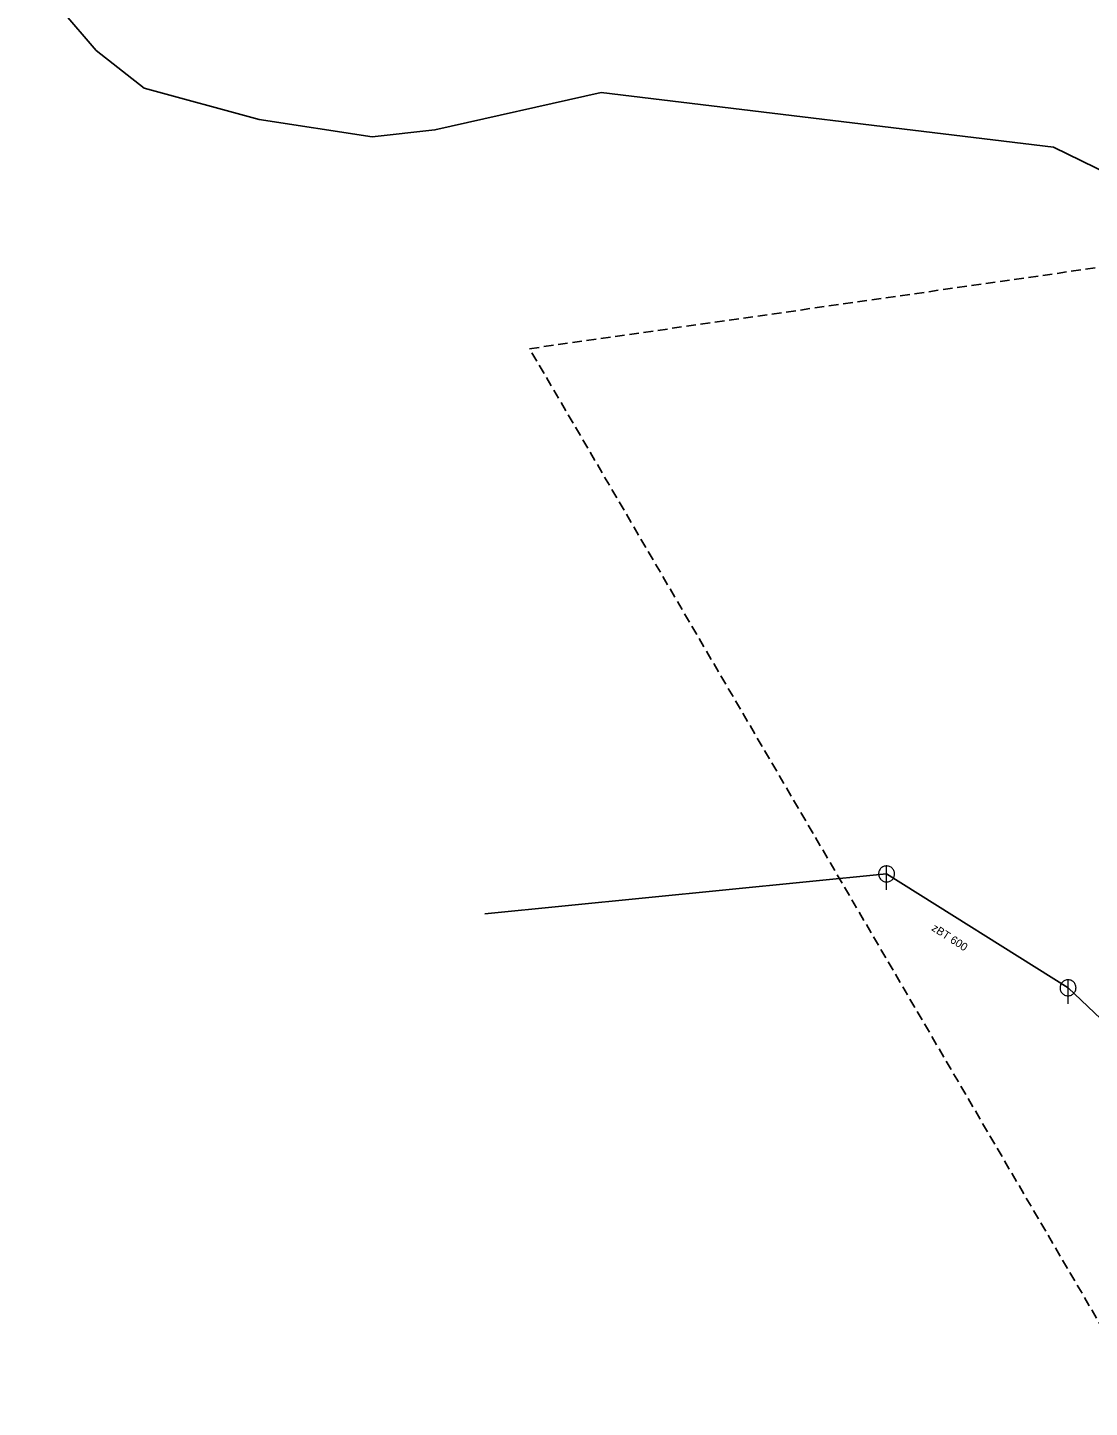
# Model space of a CAD drawing. Extents: x -687016 to -686065, y -974192 to -973552.
# Drawn here: x -686381.1 to -686248.4, y -973940.5 to -973768.1 of the extents above; entities that cross this region are included whole.
import ezdxf

# ---------------------------------------------------------------- set-up
doc = ezdxf.new("R2010")
doc.units = 0
doc.header["$LTSCALE"] = 0.4
doc.linetypes.add('MEDIUM_DASHED', pattern=[4.5, 3, -1.5])
doc.layers.add('1', color=7, linetype='Continuous')
for name, color, linetype, lineweight in [('14', 7, 'Continuous', 25), ('17', 7, 'Continuous', 25), ('22', 7, 'Continuous', 13), ('63', 7, 'MEDIUM_DASHED', 25)]:
    doc.layers.add(name, color=color, linetype=linetype, lineweight=lineweight)

msp = doc.modelspace()

# ---------------------------------------------------------------- linework, layer by layer
at = {"layer": '14'}
for p, q in [((-686273.734, -973873.852), (-686323.946, -973878.859)), ((-686251.059, -973888.086), (-686273.734, -973873.852)), ((-686232.891, -973905.396), (-686251.059, -973888.086))]:
    msp.add_line(p, q, dxfattribs=at)
at = {"layer": '17'}
msp.add_lwpolyline([(-686191.62, -973832.066), (-686200.045, -973808.813), (-686252.856, -973783.01), (-686309.416, -973776.191), (-686330.193, -973780.853), (-686338.011, -973781.713), (-686352.154, -973779.531), (-686366.52, -973775.649), (-686372.52, -973770.94), (-686381.099, -973760.889)], dxfattribs=at)
at = {"layer": '22'}
for p, q in [((-686273.734, -973875.852), (-686273.733, -973872.852)), ((-686251.059, -973890.086), (-686251.058, -973887.086))]:
    msp.add_line(p, q, dxfattribs=at)
for points in [[(-686272.734, -973873.852), (-686272.739, -973873.743), (-686272.757, -973873.635), (-686272.787, -973873.529), (-686272.827, -973873.428), (-686272.879, -973873.331), (-686272.941, -973873.241), (-686273.013, -973873.158), (-686273.093, -973873.084), (-686273.181, -973873.018), (-686273.275, -973872.963), (-686273.375, -973872.918), (-686273.48, -973872.885), (-686273.587, -973872.863), (-686273.696, -973872.853), (-686273.806, -973872.855), (-686273.914, -973872.869), (-686274.021, -973872.894), (-686274.124, -973872.931), (-686274.222, -973872.98), (-686274.314, -973873.038), (-686274.4, -973873.107), (-686274.477, -973873.184), (-686274.546, -973873.27), (-686274.605, -973873.362), (-686274.653, -973873.46), (-686274.69, -973873.563), (-686274.716, -973873.67), (-686274.73, -973873.778), (-686274.733, -973873.888), (-686274.723, -973873.997), (-686274.702, -973874.104), (-686274.668, -973874.208), (-686274.624, -973874.308), (-686274.569, -973874.403), (-686274.503, -973874.491), (-686274.429, -973874.571), (-686274.346, -973874.643), (-686274.256, -973874.705), (-686274.16, -973874.757), (-686274.058, -973874.798), (-686273.953, -973874.828), (-686273.845, -973874.846), (-686273.735, -973874.852), (-686273.626, -973874.846), (-686273.518, -973874.828), (-686273.413, -973874.799), (-686273.311, -973874.758), (-686273.214, -973874.706), (-686273.124, -973874.644), (-686273.041, -973874.573), (-686272.966, -973874.493), (-686272.901, -973874.405), (-686272.845, -973874.311), (-686272.801, -973874.211), (-686272.767, -973874.107), (-686272.745, -973873.999), (-686272.735, -973873.89)], [(-686250.059, -973888.086), (-686250.064, -973887.977), (-686250.082, -973887.869), (-686250.112, -973887.763), (-686250.152, -973887.662), (-686250.204, -973887.565), (-686250.266, -973887.475), (-686250.338, -973887.392), (-686250.418, -973887.318), (-686250.506, -973887.252), (-686250.6, -973887.197), (-686250.7, -973887.152), (-686250.805, -973887.119), (-686250.912, -973887.097), (-686251.021, -973887.087), (-686251.131, -973887.089), (-686251.239, -973887.103), (-686251.346, -973887.128), (-686251.449, -973887.165), (-686251.547, -973887.214), (-686251.639, -973887.272), (-686251.725, -973887.341), (-686251.802, -973887.418), (-686251.871, -973887.504), (-686251.93, -973887.596), (-686251.978, -973887.694), (-686252.015, -973887.797), (-686252.041, -973887.904), (-686252.055, -973888.012), (-686252.058, -973888.122), (-686252.048, -973888.231), (-686252.027, -973888.338), (-686251.993, -973888.442), (-686251.949, -973888.542), (-686251.894, -973888.637), (-686251.828, -973888.725), (-686251.754, -973888.805), (-686251.671, -973888.877), (-686251.581, -973888.939), (-686251.485, -973888.991), (-686251.383, -973889.032), (-686251.278, -973889.062), (-686251.17, -973889.08), (-686251.06, -973889.086), (-686250.951, -973889.08), (-686250.843, -973889.062), (-686250.738, -973889.033), (-686250.636, -973888.992), (-686250.539, -973888.94), (-686250.449, -973888.878), (-686250.366, -973888.807), (-686250.291, -973888.727), (-686250.226, -973888.639), (-686250.17, -973888.545), (-686250.126, -973888.445), (-686250.092, -973888.341), (-686250.07, -973888.233), (-686250.06, -973888.124)]]:
    msp.add_lwpolyline(points, close=True, dxfattribs=at)
at = {"layer": '63'}
msp.add_lwpolyline([(-686318.355, -973808.199), (-686197.373, -973790.916), (-686197.373, -973790.916), (-686115.78, -973845.177), (-686115.78, -973845.177), (-686098.497, -973969.777), (-686098.497, -973969.777), (-686210.235, -973993.089), (-686210.235, -973993.089)], close=True, dxfattribs=at)

# ---------------------------------------------------------------- texts
at = {"layer": '1'}
msp.add_text('zBT 600 ', height=1, rotation=327, dxfattribs=at).set_placement((-686268.193, -973880.844))

doc.saveas('drawing.dxf')
